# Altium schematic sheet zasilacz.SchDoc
size A4
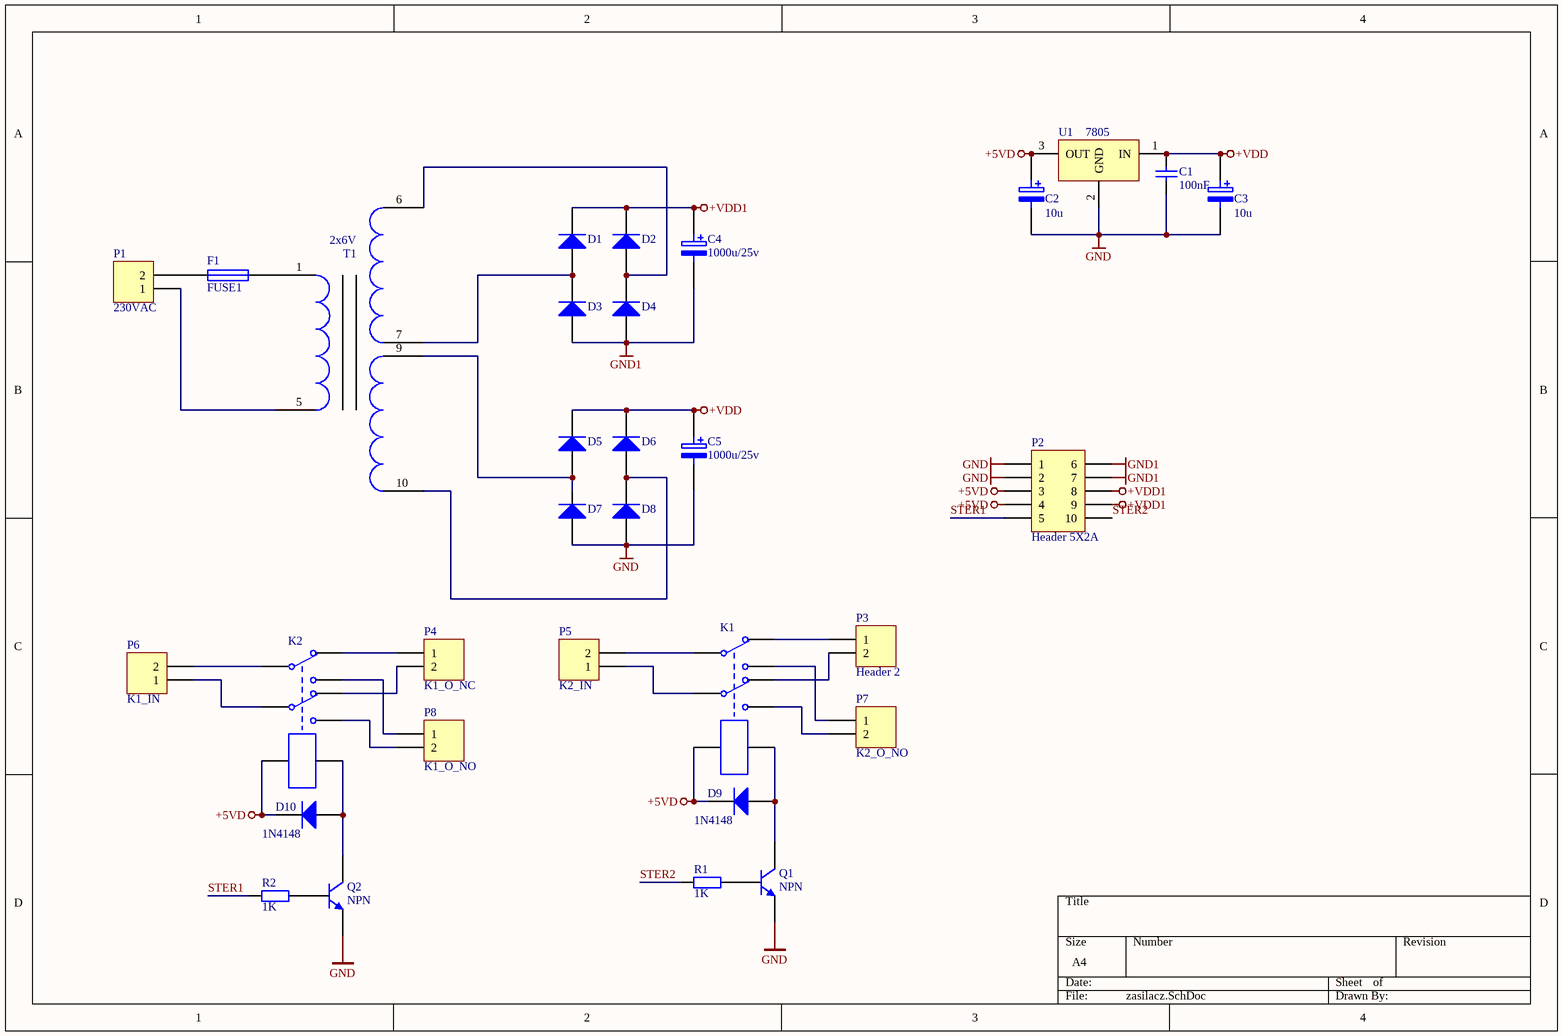
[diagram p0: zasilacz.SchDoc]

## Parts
C1  value 100nF  [C1206]  (hidden comment: Cap)
C2  10u  [3528]
C3  10u  [3528]
C4  1000u/25v  [1000u/35v]
C5  1000u/25v  [1000u/35v]
D1  (no value)  [DO-41]
D2  (no value)  [DO-41]
D3  (no value)  [DO-41]
D4  (no value)  [DO-41]
D5  (no value)  [DO-41]
D6  (no value)  [DO-41]
D7  (no value)  [DO-41]
D8  (no value)  [DO-41]
D9  1N4148  [DO-35]
D10  1N4148  [DO-35]
F1  FUSE1  [BEZP_OKR]
K1  Relay-DPDT  [Prz_big]  (value not drawn)
K2  Relay-DPDT  [Prz_big]  (value not drawn)
P1  230VAC  [ZLSRUB2-1]
P2  Header 5X2A  [HDR2X5_CEN]
P3  Header 2  [ZLSRUB2-1]
P4  K1_O_NC  [ZLSRUB2-1]
P5  K2_IN  [ZLSRUB2-1]
P6  K1_IN  [ZLSRUB2-1]
P7  K2_O_NO  [ZLSRUB2-1]
P8  K1_O_NO  [ZLSRUB2-1]
Q1  NPN  [BD139]
Q2  NPN  [BD139]
R1  1K  [1206]
R2  1K  [1206]
T1  2x6V  [TRAFO ZZ7]
U1  7805  [78XXST]

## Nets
+5VD: C2.1 D9.2(K) D10.2(K) K1.7 K2.7 P2.3 P2.4 U1.3(OUT)
+VDD: C1.2 C3.1 C5.1 D5.2(K) D6.2(K) U1.1(IN)
+VDD1: C4.1 D1.2(K) D2.2(K) P2.8 P2.9
GND: C1.1 C2.2 C3.2 C5.2 D7.1(A) D8.1(A) P2.1 P2.2 Q1.3(E) Q2.3(E) U1.2(GND)
GND1: C4.2 D3.1(A) D4.1(A) P2.6 P2.7
STER1: P2.5 R2.1
STER2: P2.10 R1.1
NetD1_1: D1.1(A) D3.2(K) T1.7
NetD2_1: D2.1(A) D4.2(K) T1.6
NetD5_1: D5.1(A) D7.2(K) T1.9
NetD6_1: D6.1(A) D8.2(K) T1.10
NetD9_1: D9.1(A) K1.8 Q1.1(C)
NetD10_1: D10.1(A) K2.8 Q2.1(C)
NetF1_1: F1.1 T1.1
NetF1_2: F1.2 P1.2
NetK1_1: K1.1 P5.2
NetK1_2: K1.2 P3.1
NetK1_3: K1.3 P7.1
NetK1_4: K1.4 P5.1
NetK1_5: K1.5 P3.2
NetK1_6: K1.6 P7.2
NetK2_1: K2.1 P6.2
NetK2_2: K2.2 P4.1
NetK2_3: K2.3 P8.1
NetK2_4: K2.4 P6.1
NetK2_5: K2.5 P4.2
NetK2_6: K2.6 P8.2
NetP1_1: P1.1 T1.5
NetQ1_2: Q1.2(B) R1.2
NetQ2_2: Q2.2(B) R2.2

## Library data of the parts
C1 = Cap: Capacitor
C2-C5 = ELECTRO2: Electrolytic Capacitor
D1-D8 = Diode 1N4007: 1 Amp General Purpose Rectifier
D9 D10 = Diode 1N4148: High Conductance Fast Diode
F1 = FUSE1: Fuse
K1 K2 = Relay-DPDT: Dual-Pole Dual-Throw Relay
P1 P3-P8 = Header 2: Header, 2-Pin
P2 = Header 5X2A: Header, 5-Pin, Dual row
Q1 Q2 = NPN: NPN Bipolar Transistor
R1 R2 = Res2: Resistor
T1 = trafo ZZ2
U1 = 78XX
